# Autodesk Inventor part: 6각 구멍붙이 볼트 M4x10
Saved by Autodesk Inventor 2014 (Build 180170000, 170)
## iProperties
Created: 2026-05
Part Number: 6각 구멍붙이 볼트 M4x10
Material: 강철, 연강
Document SubType Name: Modeling
Designer: dg
Density: 7.86 g/cm^3
Appearance: 강철
Mass: 2.0371 g
Surface Area: 3.0572 cm^2
Volume: 0.259174 cm^3
Author: jhkim
Description: 6각머리 태핑 나사
Creation Date: 2026-04-23
Sending System: Autodesk Inventor 2027
Preprocessor: ST-DEVELOPER v20.1
Author: dg
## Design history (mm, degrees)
node "6각 구멍붙이 볼트 M4x101"
body "Solid1"
node "기준1"
